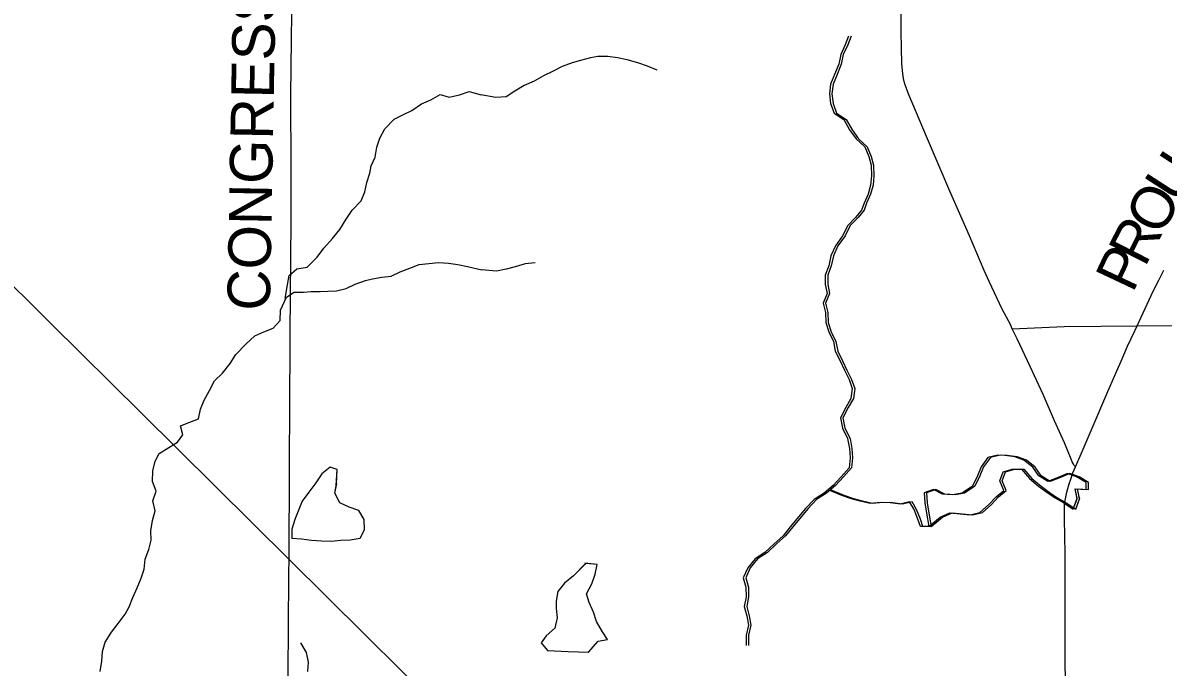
# Model space of a CAD drawing. Extents: x 0 to 34, y 0 to 22.
# Drawn here: x 16.108 to 17.627, y 7.637 to 8.496 of the extents above; entities that cross this region are included whole.
import ezdxf

# ---------------------------------------------------------------- set-up
doc = ezdxf.new("R2010")
doc.units = 0
for name, color, linetype in [('GM_X_County_Road', 7, 'Continuous'), ('GM_X_County_Road_Text', 7, 'Continuous'), ('GM_X_Minor_Lake', 7, 'Continuous'), ('GM_X_Minor_River', 7, 'Continuous'), ('GM_X_Rail_Line', 7, 'Continuous'), ('GM_X_Township_Road', 7, 'Continuous'), ('GM_X_Township_Road_Text', 7, 'Continuous')]:
    doc.layers.add(name, color=color, linetype=linetype)

msp = doc.modelspace()

# ---------------------------------------------------------------- linework, layer by layer
at = {"layer": 'GM_X_County_Road'}
msp.add_lwpolyline([(16.462, 7.6229), (16.4624, 7.6975), (16.4627, 7.7524), (16.463, 7.7909), (16.4635, 7.8942), (16.4637, 7.9239), (16.4639, 7.97), (16.4641, 8.0036), (16.4644, 8.0518), (16.4646, 8.0802), (16.4649, 8.1341), (16.4653, 8.1801), (16.4656, 8.2331), (16.4658, 8.2696), (16.4659, 8.2962), (16.466, 8.3162), (16.4659, 8.3343), (16.4655, 8.3656), (16.4655, 8.399), (16.4662, 8.4729), (16.4668, 8.5084)], dxfattribs=at)
at = {"layer": 'GM_X_Minor_Lake'}
for points in [[(17.5127, 7.8614), (17.5102, 7.8745), (17.5246, 7.8738), (17.5246, 7.8833), (17.512, 7.8905), (17.4998, 7.895), (17.4873, 7.8896), (17.4736, 7.8843), (17.4618, 7.8922), (17.4537, 7.9036), (17.4419, 7.9127), (17.4297, 7.9172), (17.4164, 7.9191), (17.4069, 7.9194), (17.3939, 7.9164), (17.3849, 7.9042), (17.38, 7.892), (17.3732, 7.8783), (17.3595, 7.8688), (17.3469, 7.8669), (17.3333, 7.8676), (17.3214, 7.874), (17.3089, 7.8694), (17.3097, 7.8561), (17.312, 7.8424), (17.3153, 7.8245)], [(17.5126, 7.8621), (17.5102, 7.8745), (17.5246, 7.8738), (17.5246, 7.8833), (17.512, 7.8905), (17.4998, 7.895), (17.4873, 7.8896), (17.4736, 7.8843), (17.4618, 7.8922), (17.4537, 7.9036), (17.4419, 7.9127), (17.4297, 7.9172), (17.4164, 7.9191), (17.4069, 7.9194), (17.3939, 7.9164), (17.3849, 7.9042), (17.38, 7.892), (17.3732, 7.8783), (17.3595, 7.8688), (17.3469, 7.8669), (17.3333, 7.8676), (17.3214, 7.874), (17.3089, 7.8694), (17.3097, 7.8561), (17.312, 7.8424), (17.3153, 7.8245)], [(17.516, 7.8614), (17.5134, 7.8745), (17.5279, 7.8738), (17.5278, 7.8833), (17.5153, 7.8905), (17.5031, 7.895), (17.4905, 7.8896), (17.4769, 7.8843), (17.465, 7.8922), (17.457, 7.9036), (17.4452, 7.9127), (17.433, 7.9172), (17.4197, 7.9191), (17.4101, 7.9194), (17.3972, 7.9164), (17.3881, 7.9042), (17.3832, 7.892), (17.3764, 7.8783), (17.3628, 7.8688), (17.3502, 7.8669), (17.3365, 7.8676), (17.3247, 7.874), (17.3122, 7.8694), (17.313, 7.8561), (17.3153, 7.8424), (17.3185, 7.8245)], [(17.5158, 7.8621), (17.5134, 7.8745), (17.5279, 7.8738), (17.5278, 7.8833), (17.5153, 7.8905), (17.5031, 7.895), (17.4905, 7.8896), (17.4769, 7.8843), (17.465, 7.8922), (17.457, 7.9036), (17.4452, 7.9127), (17.433, 7.9172), (17.4197, 7.9191), (17.4101, 7.9194), (17.3972, 7.9164), (17.3881, 7.9042), (17.3832, 7.892), (17.3764, 7.8783), (17.3628, 7.8688), (17.3502, 7.8669), (17.3365, 7.8676), (17.3247, 7.874), (17.3122, 7.8694), (17.313, 7.8561), (17.3153, 7.8424), (17.3185, 7.8245)], [(16.5259, 7.8788), (16.5271, 7.9005), (16.5179, 7.9034), (16.5066, 7.8945), (16.4987, 7.8827), (16.4893, 7.8704), (16.4806, 7.8582), (16.4709, 7.8337), (16.4665, 7.8211), (16.4666, 7.809)], [(16.526, 7.8813), (16.5271, 7.9005), (16.5179, 7.9034), (16.5066, 7.8945), (16.4987, 7.8827), (16.4893, 7.8704), (16.4806, 7.8582), (16.4709, 7.8337), (16.4665, 7.8211), (16.4666, 7.8086)], [(17.3153, 7.8245), (17.3303, 7.8368), (17.3432, 7.8429), (17.3569, 7.8414), (17.3703, 7.8399), (17.3832, 7.843), (17.3949, 7.8533), (17.4048, 7.864), (17.415, 7.8727), (17.4097, 7.8853), (17.4142, 7.8974), (17.4263, 7.9009), (17.4385, 7.9009), (17.4492, 7.8884), (17.4614, 7.8782), (17.474, 7.8691), (17.4836, 7.8627), (17.495, 7.8562), (17.5076, 7.8475), (17.5127, 7.8614)], [(17.3157, 7.8249), (17.3303, 7.8368), (17.3432, 7.8429), (17.3569, 7.8414), (17.3703, 7.8399), (17.3832, 7.843), (17.3949, 7.8533), (17.4048, 7.864), (17.415, 7.8727), (17.4097, 7.8853), (17.4142, 7.8974), (17.4263, 7.9009), (17.4385, 7.9009), (17.4492, 7.8884), (17.4614, 7.8782), (17.474, 7.8691), (17.4836, 7.8627), (17.495, 7.8562), (17.5076, 7.8475), (17.513, 7.8622)], [(17.3185, 7.8245), (17.3336, 7.8368), (17.3465, 7.8429), (17.3602, 7.8414), (17.3735, 7.8399), (17.3865, 7.843), (17.3982, 7.8533), (17.4081, 7.864), (17.4183, 7.8727), (17.4129, 7.8853), (17.4174, 7.8974), (17.4296, 7.9009), (17.4418, 7.9009), (17.4525, 7.8884), (17.4647, 7.8782), (17.4773, 7.8691), (17.4868, 7.8627), (17.4983, 7.8562), (17.5109, 7.8475), (17.516, 7.8614)], [(17.3189, 7.8249), (17.3336, 7.8368), (17.3465, 7.8429), (17.3602, 7.8414), (17.3735, 7.8399), (17.3865, 7.843), (17.3982, 7.8533), (17.4081, 7.864), (17.4183, 7.8727), (17.4129, 7.8853), (17.4174, 7.8974), (17.4296, 7.9009), (17.4418, 7.9009), (17.4525, 7.8884), (17.4647, 7.8782), (17.4773, 7.8691), (17.4868, 7.8627), (17.4983, 7.8562), (17.5109, 7.8475), (17.5162, 7.8622)], [(16.4666, 7.809), (16.4795, 7.8079), (16.4928, 7.8065), (16.5062, 7.8054), (16.5191, 7.8048), (16.532, 7.8064), (16.5446, 7.8069), (16.5575, 7.8089), (16.5635, 7.8203), (16.563, 7.834), (16.556, 7.8458), (16.5431, 7.8503), (16.5305, 7.8559), (16.5239, 7.8691), (16.5259, 7.8788)], [(16.4667, 7.809), (16.4795, 7.8079), (16.4928, 7.8065), (16.5062, 7.8054), (16.5191, 7.8048), (16.532, 7.8064), (16.5446, 7.8069), (16.5575, 7.8089), (16.5635, 7.8203), (16.563, 7.834), (16.556, 7.8458), (16.5431, 7.8503), (16.5305, 7.8559), (16.5239, 7.8691), (16.5265, 7.8817)], [(16.8581, 7.7754), (16.8417, 7.7587), (16.8299, 7.7492), (16.8212, 7.7378), (16.819, 7.7249), (16.8186, 7.7154), (16.8202, 7.7028), (16.8168, 7.6892), (16.8055, 7.6789), (16.7986, 7.6694), (16.8074, 7.6595), (16.8348, 7.6581), (16.8485, 7.6577), (16.8617, 7.657)], [(16.8574, 7.7746), (16.8417, 7.7587), (16.8299, 7.7492), (16.8212, 7.7378), (16.819, 7.7249), (16.8186, 7.7154), (16.8202, 7.7028), (16.8168, 7.6892), (16.8055, 7.6789), (16.7986, 7.6694), (16.8074, 7.6595), (16.8348, 7.6581), (16.8485, 7.6577), (16.8622, 7.657)], [(16.8617, 7.657), (16.8747, 7.6718), (16.8873, 7.6738), (16.8804, 7.684), (16.8723, 7.698), (16.8685, 7.7106), (16.8627, 7.7231), (16.8593, 7.7349), (16.8665, 7.7482), (16.8706, 7.7611), (16.8736, 7.774), (16.8572, 7.7755)], [(16.8617, 7.657), (16.8747, 7.6718), (16.8873, 7.6738), (16.8804, 7.684), (16.8723, 7.698), (16.8685, 7.7106), (16.8627, 7.7231), (16.8593, 7.7349), (16.8665, 7.7482), (16.8706, 7.7611), (16.8736, 7.774), (16.8581, 7.7754)]]:
    msp.add_lwpolyline(points, dxfattribs=at)
at = {"layer": 'GM_X_Minor_River'}
for points in [[(17.2084, 8.4776), (17.2039, 8.4662), (17.1979, 8.4532), (17.1953, 8.4403), (17.1896, 8.4266), (17.1843, 8.4137), (17.1828, 8.4008), (17.1844, 8.3879), (17.189, 8.375), (17.202, 8.3667), (17.2097, 8.353), (17.2185, 8.3409), (17.2299, 8.3303), (17.2353, 8.3174), (17.2384, 8.306), (17.2388, 8.2919), (17.2377, 8.2794), (17.2343, 8.2672), (17.2291, 8.2555), (17.2257, 8.246), (17.2177, 8.2364), (17.2071, 8.2254), (17.2003, 8.2117), (17.1908, 8.1984), (17.1848, 8.1851), (17.1818, 8.1718), (17.1773, 8.1596), (17.1773, 8.1471), (17.1797, 8.1349), (17.1744, 8.122), (17.1775, 8.1095), (17.1779, 8.0962), (17.1818, 8.084), (17.1883, 8.0711), (17.1906, 8.0582), (17.1971, 8.0453), (17.2029, 8.0328), (17.209, 8.0203), (17.2132, 8.0082), (17.2114, 7.9949), (17.2046, 7.9831), (17.1974, 7.9694), (17.2001, 7.9557), (17.207, 7.9417), (17.2094, 7.9284), (17.2102, 7.9159), (17.2091, 7.9029), (17.1985, 7.8908), (17.1879, 7.879), (17.1757, 7.869), (17.1624, 7.8603), (17.1511, 7.8485), (17.1306, 7.8241), (17.1211, 7.8119), (17.109, 7.8013), (17.0969, 7.7898), (17.084, 7.7814), (17.0741, 7.7693), (17.0681, 7.7563), (17.0716, 7.7438), (17.072, 7.7309), (17.0694, 7.718), (17.0728, 7.7054), (17.0748, 7.6929), (17.0718, 7.6796), (17.0718, 7.6659)], [(17.2117, 8.4776), (17.2072, 8.4662), (17.2011, 8.4532), (17.1985, 8.4403), (17.1929, 8.4266), (17.1876, 8.4137), (17.1861, 8.4008), (17.1877, 8.3879), (17.1923, 8.375), (17.2053, 8.3667), (17.2129, 8.353), (17.2217, 8.3409), (17.2332, 8.3303), (17.2386, 8.3174), (17.2416, 8.306), (17.2421, 8.2919), (17.241, 8.2794), (17.2376, 8.2672), (17.2323, 8.2555), (17.2289, 8.246), (17.221, 8.2364), (17.2104, 8.2254), (17.2036, 8.2117), (17.1941, 8.1984), (17.1881, 8.1851), (17.1851, 8.1718), (17.1806, 8.1596), (17.1806, 8.1471), (17.1829, 8.1349), (17.1777, 8.122), (17.1807, 8.1095), (17.1812, 8.0962), (17.185, 8.084), (17.1915, 8.0711), (17.1939, 8.0582), (17.2004, 8.0453), (17.2061, 8.0328), (17.2123, 8.0203), (17.2165, 8.0082), (17.2147, 7.9949), (17.2079, 7.9831), (17.2007, 7.9694), (17.2034, 7.9557), (17.2103, 7.9417), (17.2126, 7.9284), (17.2134, 7.9159), (17.2123, 7.9029), (17.2017, 7.8908), (17.1911, 7.879), (17.179, 7.869), (17.1657, 7.8603), (17.1543, 7.8485), (17.1339, 7.8241), (17.1244, 7.8119), (17.1123, 7.8013), (17.1001, 7.7898), (17.0872, 7.7814), (17.0774, 7.7693), (17.0713, 7.7563), (17.0748, 7.7438), (17.0752, 7.7309), (17.0726, 7.718), (17.0761, 7.7054), (17.0781, 7.6929), (17.0751, 7.6796), (17.0751, 7.6659)], [(16.9533, 8.4324), (16.9403, 8.4377), (16.9274, 8.4423), (16.9133, 8.4464), (16.9007, 8.449), (16.8878, 8.4505), (16.8741, 8.4508), (16.8646, 8.4489), (16.8513, 8.4455), (16.8399, 8.4424), (16.8266, 8.4374), (16.814, 8.4309), (16.8019, 8.4248), (16.7893, 8.4179), (16.7761, 8.4122), (16.7639, 8.4046), (16.7521, 8.397), (16.7384, 8.3962), (16.7186, 8.3996)], [(16.458, 8.1284), (16.4608, 8.1465), (16.463, 8.1591), (16.4732, 8.1679), (16.4869, 8.1699), (16.5004, 8.1833), (16.5095, 8.1952), (16.5208, 8.2082), (16.5306, 8.2201), (16.5392, 8.2339), (16.5471, 8.2461), (16.5592, 8.2584), (16.564, 8.2706), (16.5666, 8.2828), (16.5707, 8.2954), (16.5725, 8.3049), (16.5777, 8.3164), (16.5799, 8.3301), (16.584, 8.3419), (16.5904, 8.3545), (16.6028, 8.3672), (16.6146, 8.373), (16.6267, 8.3788), (16.6395, 8.3876), (16.6517, 8.393), (16.6642, 8.4), (16.6764, 8.3967), (16.69, 8.3998), (16.7027, 8.4043), (16.7187, 8.3996)], [(16.2116, 7.6315), (16.2134, 7.6449), (16.2145, 7.6578), (16.2182, 7.6704), (16.2264, 7.6838), (16.2355, 7.6953), (16.2445, 7.7079), (16.2501, 7.7175), (16.255, 7.7301), (16.2606, 7.7427), (16.2662, 7.7557), (16.2699, 7.7675), (16.2713, 7.7808), (16.2761, 7.7938), (16.2791, 7.8064), (16.279, 7.8189), (16.2811, 7.8327), (16.2845, 7.8452), (16.2817, 7.8585), (16.2861, 7.8715), (16.2811, 7.8844), (16.2817, 7.8985), (16.2847, 7.9115), (16.2899, 7.9218), (16.3028, 7.9299), (16.3142, 7.9368), (16.3213, 7.9468), (16.3182, 7.9585), (16.3307, 7.9636), (16.3424, 7.9679), (16.345, 7.9808), (16.3498, 7.993), (16.357, 8.0056), (16.3637, 8.0186), (16.3743, 8.0286), (16.3844, 8.0416), (16.3923, 8.0539), (16.4052, 8.0673), (16.4172, 8.0784), (16.4294, 8.0838), (16.4419, 8.0889), (16.4513, 8.0989), (16.4516, 8.1126), (16.4598, 8.1301), (16.47, 8.1367), (16.4822, 8.1368), (16.4924, 8.1376), (16.5046, 8.1377), (16.5145, 8.1382), (16.5263, 8.1386), (16.5392, 8.1418), (16.5509, 8.1472), (16.5646, 8.1522), (16.5741, 8.1546), (16.5866, 8.1566), (16.5992, 8.1582), (16.6109, 8.164), (16.6238, 8.1687), (16.6363, 8.1737), (16.6622, 8.1762), (16.6755, 8.1755), (16.6877, 8.1737), (16.7006, 8.1708), (16.72, 8.1667)], [(16.791, 8.176), (16.7777, 8.1745), (16.7644, 8.1703), (16.7522, 8.1672), (16.7393, 8.1645), (16.72, 8.1667)], [(16.7264, 8.1695), (16.7265, 8.1695)], [(17.3163, 7.8246), (17.3041, 7.8246), (17.3007, 7.8341), (17.2957, 7.847), (17.2895, 7.8572), (17.277, 7.8541), (17.2637, 7.856), (17.2507, 7.8567), (17.237, 7.8552), (17.2237, 7.8582), (17.2123, 7.8615), (17.1993, 7.8657), (17.1812, 7.8735)], [(17.3196, 7.8246), (17.3074, 7.8246), (17.3039, 7.8341), (17.2989, 7.847), (17.2928, 7.8572), (17.2803, 7.8541), (17.2669, 7.856), (17.254, 7.8567), (17.2403, 7.8552), (17.227, 7.8582), (17.2155, 7.8615), (17.2026, 7.8657), (17.1844, 7.8735)], [(16.4882, 7.6314), (16.4888, 7.6439), (16.4861, 7.6565), (16.4787, 7.6694)]]:
    msp.add_lwpolyline(points, dxfattribs=at)
at = {"layer": 'GM_X_Rail_Line'}
msp.add_lwpolyline([(15.8135, 8.4241), (15.8666, 8.3714), (15.9854, 8.2541), (16.1458, 8.0951), (16.2661, 7.976), (16.4634, 7.7803), (16.7137, 7.5325), (16.7661, 7.4804), (16.7923, 7.4559), (16.8194, 7.4321), (16.8443, 7.412), (16.8673, 7.3945), (16.9054, 7.3674), (17.0025, 7.3002), (17.2767, 7.111), (17.3271, 7.0801), (17.3744, 7.0548), (17.4188, 7.0339), (17.4375, 7.0259), (17.4558, 7.0187), (17.4812, 7.009), (17.6636, 6.9463)], dxfattribs=at)
at = {"layer": 'GM_X_Township_Road'}
for points in [[(17.4263, 8.088), (17.4238, 8.0935), (17.4127, 8.1139), (17.3954, 8.1509), (17.3888, 8.1658), (17.3694, 8.2119), (17.3431, 8.2714), (17.3133, 8.3411), (17.2878, 8.4017), (17.285, 8.4094), (17.2838, 8.4131), (17.2825, 8.4175), (17.2816, 8.4215), (17.2806, 8.4277), (17.2793, 8.4413), (17.2786, 8.4624), (17.2784, 8.4836), (17.2778, 8.6369)], [(17.5104, 7.9038), (17.518, 7.9214), (17.5327, 7.9556), (17.5525, 8.0012), (17.5642, 8.0286), (17.5712, 8.0447), (17.5798, 8.0648), (17.5895, 8.085), (17.5927, 8.092), (17.6139, 8.1379), (17.6214, 8.1529), (17.6281, 8.1661)], [(17.4263, 8.088), (17.4955, 8.0912), (17.5927, 8.092), (17.6463, 8.0924)], [(17.4978, 7.5437), (17.4968, 7.6607), (17.4967, 7.7886), (17.4959, 7.8347), (17.4961, 7.853), (17.4965, 7.8569), (17.4973, 7.8612), (17.4982, 7.8658), (17.4991, 7.8702), (17.5004, 7.8753), (17.502, 7.8812), (17.5042, 7.8878), (17.5071, 7.8959), (17.5104, 7.9038), (17.5085, 7.9062), (17.5073, 7.9084), (17.5061, 7.9106), (17.505, 7.9144), (17.4957, 7.9361), (17.4828, 7.9652), (17.4676, 8.0002), (17.4503, 8.0375), (17.4327, 8.0746), (17.4263, 8.088)]]:
    msp.add_lwpolyline(points, dxfattribs=at)

# ---------------------------------------------------------------- texts
at = {"layer": 'GM_X_County_Road_Text'}
msp.add_text('CONGRESS', height=0.05682, rotation=88.9462, dxfattribs=at).set_placement((16.4374, 8.1117))
at = {"layer": 'GM_X_Township_Road_Text'}
for s, rotation, p in [('U', 57.1667, (17.6478, 8.2527)), ('O', 60.8601, (17.6239, 8.2099)), ('R', 62.9462, (17.603, 8.1688)), ('P', 64.7568, (17.5868, 8.1345))]:
    msp.add_text(s, height=0.0568, rotation=rotation, dxfattribs=at).set_placement(p)

doc.saveas('drawing.dxf')
